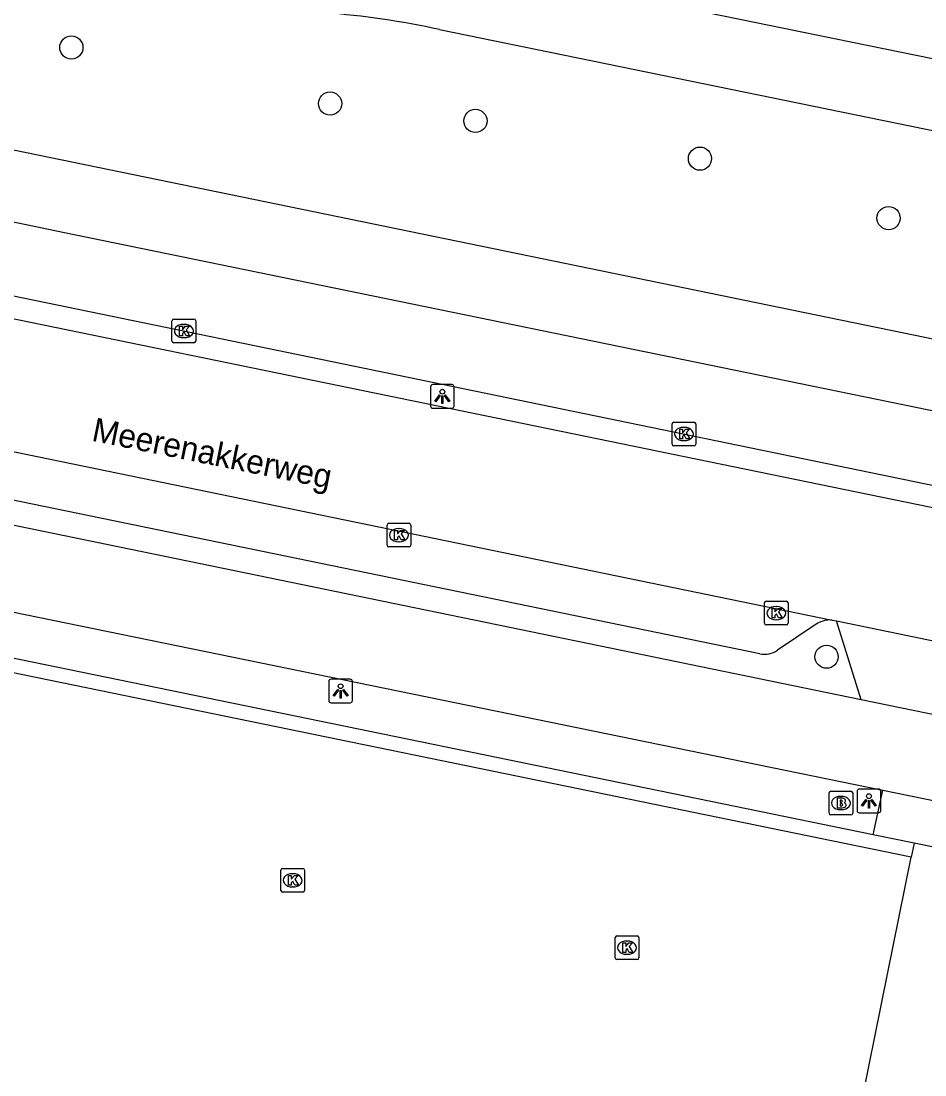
# Model space of a CAD drawing. Extents: x 157692 to 159670, y 381454 to 383289.
# Drawn here: x 158620.7 to 158658.83, y 382055.97 to 382100.44 of the extents above; entities that cross this region are included whole.
import ezdxf

# ---------------------------------------------------------------- set-up
doc = ezdxf.new("R2010")
doc.units = 0
for name, color, linetype in [('IMGEO_Boom', 7, 'Continuous'), ('IMGEO_Brandkraan', 7, 'Continuous'), ('IMGEO_Fietspad_gesloten', 7, 'Continuous'), ('IMGEO_Haag', 7, 'Continuous'), ('IMGEO_Kolk', 7, 'Continuous'), ('IMGEO_Lichtpunt', 7, 'Continuous'), ('IMGEO_Openbare_ruimte_label', 7, 'Continuous'), ('IMGEO_Parkeervlak_open', 7, 'Continuous'), ('IMGEO_Rijbaan_lokaal_open', 7, 'Continuous'), ('IMGEO_Rijbaan_regionaal_gesloten', 7, 'Continuous'), ('IMGEO_Voetpad_open', 7, 'Continuous')]:
    doc.layers.add(name, color=color, linetype=linetype)

msp = doc.modelspace()

# ---------------------------------------------------------------- linework, layer by layer
at = {"layer": 'IMGEO_Boom'}
for centre in [(158622.819, 382099.321), (158633.736, 382096.955), (158639.866, 382096.224), (158649.338, 382094.631), (158657.295, 382092.122), (158654.68, 382073.617)]:
    msp.add_circle(centre, 0.489, dxfattribs=at)
at = {"layer": 'IMGEO_Brandkraan'}
for p, q in [((158654.783, 382067.016), (158654.783, 382067.868)), ((158654.858, 382067.942), (158655.71, 382067.942)), ((158655.271, 382067.722), (158655.296, 382067.722)), ((158655.784, 382067.868), (158655.784, 382067.016)), ((158655.294, 382067.162), (158655.269, 382067.162)), ((158655.71, 382066.942), (158654.858, 382066.942))]:
    msp.add_line(p, q, dxfattribs=at)
for points in [[(158654.783, 382067.016), (158654.783, 382067.868)], [(158654.858, 382067.942), (158655.71, 382067.942)], [(158655.131, 382067.642), (158655.131, 382067.242), (158655.344, 382067.242)], [(158655.362, 382067.642), (158655.131, 382067.642)], [(158655.784, 382067.868), (158655.784, 382067.016)], [(158655.31, 382067.561), (158655.256, 382067.561), (158655.256, 382067.485)], [(158655.256, 382067.485), (158655.309, 382067.485)], [(158655.318, 382067.409), (158655.256, 382067.409), (158655.256, 382067.328)], [(158655.256, 382067.328), (158655.318, 382067.328)], [(158655.71, 382066.942), (158654.858, 382066.942)]]:
    msp.add_lwpolyline(points, dxfattribs=at)
for centre, radius, start, end in [((158654.86, 382067.866), 0.0765, 91.552, 178.448), ((158654.86, 382067.866), 0.0765, 91.552, 178.448), ((158655.366, 382067.497), 0.145, 59.4692, 91.5367), ((158655.391, 382067.544), 0.0922, 285.5137, 58.1501), ((158655.708, 382067.866), 0.0765, 1.552, 88.448), ((158655.708, 382067.866), 0.0765, 1.552, 88.448), ((158655.311, 382067.523), 0.0379, 267.8285, 90.9355), ((158655.319, 382067.368), 0.0404, 269.8759, 90.5077), ((158655.35, 382067.493), 0.251, 268.6676, 293.5347), ((158655.396, 382067.352), 0.105, 301.3115, 78.989), ((158654.86, 382067.018), 0.0765, 181.552, 268.448), ((158654.86, 382067.018), 0.0765, 181.552, 268.448), ((158655.708, 382067.018), 0.0765, 271.552, 358.448), ((158655.708, 382067.018), 0.0765, 271.552, 358.448)]:
    msp.add_arc(centre, radius, start, end, dxfattribs=at)
for centre, major_axis, ratio, start_param, end_param in [((158655.27, 382067.442), (-0.387, 0.002), 0.722429, 4.712389, 7.853982), ((158655.295, 382067.442), (-0.39, 0.002), 0.717154, 1.570796, 4.712389)]:
    msp.add_ellipse(centre, major_axis=major_axis, ratio=ratio, start_param=start_param, end_param=end_param, dxfattribs=at)
at = {"layer": 'IMGEO_Fietspad_gesloten'}
for points in [[(158533.524, 382092.807), (158567.173, 382086.396), (158657.056, 382067.984)], [(158656.145, 382071.8), (158599.36, 382083.49)], [(158657.056, 382067.984), (158692.348, 382060.756)]]:
    msp.add_lwpolyline(points, dxfattribs=at)
at = {"layer": 'IMGEO_Haag'}
msp.add_lwpolyline([(158658.251, 382065.165), (158656.531, 382065.514), (158574.936, 382082.265), (158570.839, 382083.106), (158565.823, 382083.768), (158561.047, 382084.02), (158557.322, 382083.532), (158553.579, 382082.999), (158549.351, 382081.923), (158544.304, 382079.926), (158539.307, 382077.53)], dxfattribs=at)
at = {"layer": 'IMGEO_Kolk'}
for p, q in [((158627.065, 382086.934), (158627.065, 382087.786)), ((158627.14, 382087.86), (158627.992, 382087.86)), ((158627.553, 382087.64), (158627.578, 382087.64)), ((158628.066, 382087.786), (158628.066, 382086.934)), ((158627.992, 382086.86), (158627.14, 382086.86)), ((158627.576, 382087.08), (158627.551, 382087.08)), ((158648.164, 382082.587), (158648.164, 382083.439)), ((158648.239, 382083.513), (158649.091, 382083.513)), ((158648.652, 382083.293), (158648.677, 382083.293)), ((158649.165, 382083.439), (158649.165, 382082.587)), ((158648.675, 382082.733), (158648.65, 382082.733)), ((158649.091, 382082.513), (158648.239, 382082.513)), ((158636.137, 382078.32), (158636.137, 382079.172)), ((158636.212, 382079.246), (158637.064, 382079.246)), ((158637.138, 382079.172), (158637.138, 382078.32)), ((158636.625, 382079.026), (158636.65, 382079.026)), ((158636.648, 382078.466), (158636.623, 382078.466)), ((158637.064, 382078.246), (158636.212, 382078.246)), ((158652.058, 382075.031), (158652.058, 382075.883)), ((158652.133, 382075.957), (158652.985, 382075.957)), ((158652.546, 382075.737), (158652.571, 382075.737)), ((158653.059, 382075.883), (158653.059, 382075.031)), ((158652.569, 382075.177), (158652.544, 382075.177)), ((158652.985, 382074.957), (158652.133, 382074.957)), ((158631.655, 382063.755), (158631.655, 382064.607)), ((158631.73, 382064.681), (158632.582, 382064.681)), ((158632.656, 382064.607), (158632.656, 382063.755)), ((158632.143, 382064.461), (158632.168, 382064.461)), ((158632.582, 382063.681), (158631.73, 382063.681)), ((158632.166, 382063.901), (158632.141, 382063.901)), ((158645.836, 382061.839), (158646.688, 382061.839)), ((158645.761, 382060.913), (158645.761, 382061.765)), ((158646.249, 382061.619), (158646.274, 382061.619)), ((158646.762, 382061.765), (158646.762, 382060.913)), ((158646.272, 382061.059), (158646.247, 382061.059)), ((158646.688, 382060.839), (158645.836, 382060.839))]:
    msp.add_line(p, q, dxfattribs=at)
for points in [[(158627.065, 382086.934), (158627.065, 382087.786)], [(158627.14, 382087.86), (158627.992, 382087.86)], [(158628.066, 382087.786), (158628.066, 382086.934)], [(158627.386, 382087.56), (158627.509, 382087.56), (158627.509, 382087.409), (158627.639, 382087.56), (158627.803, 382087.56), (158627.657, 382087.409), (158627.81, 382087.16), (158627.658, 382087.16), (158627.573, 382087.324), (158627.509, 382087.257), (158627.509, 382087.16), (158627.386, 382087.16), (158627.386, 382087.56)], [(158627.992, 382086.86), (158627.14, 382086.86)], [(158648.164, 382082.587), (158648.164, 382083.439)], [(158648.239, 382083.513), (158649.091, 382083.513)], [(158648.485, 382083.213), (158648.608, 382083.213), (158648.608, 382083.062), (158648.738, 382083.213), (158648.902, 382083.213), (158648.756, 382083.062), (158648.909, 382082.813), (158648.757, 382082.813), (158648.672, 382082.977), (158648.608, 382082.91), (158648.608, 382082.813), (158648.485, 382082.813), (158648.485, 382083.213)], [(158649.165, 382083.439), (158649.165, 382082.587)], [(158649.091, 382082.513), (158648.239, 382082.513)], [(158636.137, 382078.32), (158636.137, 382079.172)], [(158636.212, 382079.246), (158637.064, 382079.246)], [(158637.138, 382079.172), (158637.138, 382078.32)], [(158636.458, 382078.946), (158636.581, 382078.946), (158636.581, 382078.795), (158636.711, 382078.946), (158636.875, 382078.946), (158636.729, 382078.795), (158636.882, 382078.546), (158636.73, 382078.546), (158636.645, 382078.71), (158636.581, 382078.643), (158636.581, 382078.546), (158636.458, 382078.546), (158636.458, 382078.946)], [(158637.064, 382078.246), (158636.212, 382078.246)], [(158652.058, 382075.031), (158652.058, 382075.883)], [(158652.133, 382075.957), (158652.985, 382075.957)], [(158652.379, 382075.657), (158652.502, 382075.657), (158652.502, 382075.506), (158652.632, 382075.657), (158652.796, 382075.657), (158652.65, 382075.506), (158652.803, 382075.257), (158652.651, 382075.257), (158652.566, 382075.421), (158652.502, 382075.354), (158652.502, 382075.257), (158652.379, 382075.257), (158652.379, 382075.657)], [(158653.059, 382075.883), (158653.059, 382075.031)], [(158652.985, 382074.957), (158652.133, 382074.957)], [(158631.655, 382063.755), (158631.655, 382064.607)], [(158631.73, 382064.681), (158632.582, 382064.681)], [(158632.656, 382064.607), (158632.656, 382063.755)], [(158631.976, 382064.381), (158632.099, 382064.381), (158632.099, 382064.23), (158632.229, 382064.381), (158632.393, 382064.381), (158632.247, 382064.23), (158632.4, 382063.981), (158632.248, 382063.981), (158632.163, 382064.145), (158632.099, 382064.078), (158632.099, 382063.981), (158631.976, 382063.981), (158631.976, 382064.381)], [(158632.582, 382063.681), (158631.73, 382063.681)], [(158645.836, 382061.839), (158646.688, 382061.839)], [(158645.761, 382060.913), (158645.761, 382061.765)], [(158646.082, 382061.539), (158646.205, 382061.539), (158646.205, 382061.388), (158646.335, 382061.539), (158646.499, 382061.539), (158646.353, 382061.388), (158646.506, 382061.139), (158646.354, 382061.139), (158646.269, 382061.303), (158646.205, 382061.236), (158646.205, 382061.139), (158646.082, 382061.139), (158646.082, 382061.539)], [(158646.762, 382061.765), (158646.762, 382060.913)], [(158646.688, 382060.839), (158645.836, 382060.839)]]:
    msp.add_lwpolyline(points, dxfattribs=at)
for centre, start, end in [((158627.142, 382087.784), 91.552, 178.448), ((158627.142, 382087.784), 91.552, 178.448), ((158627.99, 382087.784), 1.552, 88.448), ((158627.99, 382087.784), 1.552, 88.448), ((158627.142, 382086.936), 181.552, 268.448), ((158627.142, 382086.936), 181.552, 268.448), ((158627.99, 382086.936), 271.552, 358.448), ((158627.99, 382086.936), 271.552, 358.448), ((158648.241, 382083.437), 91.552, 178.448), ((158648.241, 382083.437), 91.552, 178.448), ((158649.089, 382083.437), 1.552, 88.448), ((158649.089, 382083.437), 1.552, 88.448), ((158648.241, 382082.589), 181.552, 268.448), ((158648.241, 382082.589), 181.552, 268.448), ((158649.089, 382082.589), 271.552, 358.448), ((158649.089, 382082.589), 271.552, 358.448), ((158636.214, 382079.17), 91.552, 178.448), ((158636.214, 382079.17), 91.552, 178.448), ((158637.062, 382079.17), 1.552, 88.448), ((158637.062, 382079.17), 1.552, 88.448), ((158636.214, 382078.322), 181.552, 268.448), ((158636.214, 382078.322), 181.552, 268.448), ((158637.062, 382078.322), 271.552, 358.448), ((158637.062, 382078.322), 271.552, 358.448), ((158652.135, 382075.881), 91.552, 178.448), ((158652.135, 382075.881), 91.552, 178.448), ((158652.983, 382075.881), 1.552, 88.448), ((158652.983, 382075.881), 1.552, 88.448), ((158652.135, 382075.033), 181.552, 268.448), ((158652.135, 382075.033), 181.552, 268.448), ((158652.983, 382075.033), 271.552, 358.448), ((158652.983, 382075.033), 271.552, 358.448), ((158631.732, 382064.605), 91.552, 178.448), ((158631.732, 382064.605), 91.552, 178.448), ((158632.58, 382064.605), 1.552, 88.448), ((158632.58, 382064.605), 1.552, 88.448), ((158631.732, 382063.757), 181.552, 268.448), ((158631.732, 382063.757), 181.552, 268.448), ((158632.58, 382063.757), 271.552, 358.448), ((158632.58, 382063.757), 271.552, 358.448), ((158645.838, 382061.763), 91.552, 178.448), ((158645.838, 382061.763), 91.552, 178.448), ((158646.686, 382061.763), 1.552, 88.448), ((158646.686, 382061.763), 1.552, 88.448), ((158645.838, 382060.915), 181.552, 268.448), ((158645.838, 382060.915), 181.552, 268.448), ((158646.686, 382060.915), 271.552, 358.448), ((158646.686, 382060.915), 271.552, 358.448)]:
    msp.add_arc(centre, 0.0765, start, end, dxfattribs=at)
for centre, major_axis, ratio, start_param, end_param in [((158627.552, 382087.36), (-0.387, 0.002), 0.722429, 4.712389, 7.853982), ((158627.577, 382087.36), (-0.39, 0.002), 0.717154, 1.570796, 4.712389), ((158648.651, 382083.013), (-0.387, 0.002), 0.722429, 4.712389, 7.853982), ((158648.676, 382083.013), (-0.39, 0.002), 0.717154, 1.570796, 4.712389), ((158636.624, 382078.746), (-0.387, 0.002), 0.722429, 4.712389, 7.853982), ((158636.649, 382078.746), (-0.39, 0.002), 0.717154, 1.570796, 4.712389), ((158652.545, 382075.457), (-0.387, 0.002), 0.722429, 4.712389, 7.853982), ((158652.57, 382075.457), (-0.39, 0.002), 0.717154, 1.570796, 4.712389), ((158632.142, 382064.181), (-0.387, 0.002), 0.722429, 4.712389, 7.853982), ((158632.167, 382064.181), (-0.39, 0.002), 0.717154, 1.570796, 4.712389), ((158646.248, 382061.339), (-0.387, 0.002), 0.722429, 4.712389, 7.853982), ((158646.273, 382061.339), (-0.39, 0.002), 0.717154, 1.570796, 4.712389)]:
    msp.add_ellipse(centre, major_axis=major_axis, ratio=ratio, start_param=start_param, end_param=end_param, dxfattribs=at)
at = {"layer": 'IMGEO_Lichtpunt'}
for p, q in [((158637.971, 382085.001), (158637.971, 382084.194)), ((158637.971, 382085.001), (158637.971, 382084.194)), ((158638.873, 382085.096), (158638.065, 382085.096)), ((158638.873, 382085.096), (158638.065, 382085.096)), ((158638.967, 382084.194), (158638.967, 382085.001)), ((158638.967, 382084.194), (158638.967, 382085.001)), ((158638.065, 382084.1), (158638.873, 382084.1)), ((158638.065, 382084.1), (158638.873, 382084.1)), ((158633.681, 382072.574), (158633.681, 382071.767)), ((158633.681, 382072.574), (158633.681, 382071.767)), ((158634.583, 382072.669), (158633.775, 382072.669)), ((158634.583, 382072.669), (158633.775, 382072.669)), ((158634.677, 382071.767), (158634.677, 382072.574)), ((158634.677, 382071.767), (158634.677, 382072.574)), ((158633.775, 382071.673), (158634.583, 382071.673)), ((158633.775, 382071.673), (158634.583, 382071.673)), ((158655.966, 382067.934), (158655.966, 382067.127)), ((158655.966, 382067.934), (158655.966, 382067.127)), ((158656.868, 382068.029), (158656.06, 382068.029)), ((158656.868, 382068.029), (158656.06, 382068.029)), ((158656.962, 382067.127), (158656.962, 382067.934)), ((158656.962, 382067.127), (158656.962, 382067.934)), ((158656.06, 382067.033), (158656.868, 382067.033)), ((158656.06, 382067.033), (158656.868, 382067.033))]:
    msp.add_line(p, q, dxfattribs=at)
for points in [[(158638.345, 382084.665), (158638.384, 382084.637), (158638.196, 382084.375), (158638.158, 382084.402), (158638.345, 382084.665)], [(158638.447, 382084.617), (158638.494, 382084.617), (158638.494, 382084.295), (158638.447, 382084.295), (158638.447, 382084.617)], [(158638.557, 382084.637), (158638.595, 382084.664), (158638.782, 382084.402), (158638.743, 382084.374), (158638.557, 382084.637)], [(158634.055, 382072.238), (158634.094, 382072.21), (158633.906, 382071.948), (158633.868, 382071.975), (158634.055, 382072.238)], [(158634.157, 382072.19), (158634.204, 382072.19), (158634.204, 382071.868), (158634.157, 382071.868), (158634.157, 382072.19)], [(158634.267, 382072.21), (158634.305, 382072.237), (158634.492, 382071.975), (158634.453, 382071.947), (158634.267, 382072.21)], [(158656.34, 382067.598), (158656.379, 382067.57), (158656.191, 382067.308), (158656.153, 382067.335), (158656.34, 382067.598)], [(158656.552, 382067.57), (158656.59, 382067.597), (158656.777, 382067.335), (158656.738, 382067.307), (158656.552, 382067.57)], [(158656.442, 382067.55), (158656.489, 382067.55), (158656.489, 382067.228), (158656.442, 382067.228), (158656.442, 382067.55)]]:
    msp.add_lwpolyline(points, dxfattribs=at)
for centre in [(158638.47, 382084.799), (158634.18, 382072.372), (158656.465, 382067.732)]:
    msp.add_circle(centre, 0.0994, dxfattribs=at)
for centre, start, end in [((158638.065, 382085.001), 90, 180), ((158638.065, 382085.001), 90, 180), ((158638.873, 382085.001), 0, 90), ((158638.873, 382085.001), 0, 90), ((158638.065, 382084.194), 180, 270), ((158638.065, 382084.194), 180, 270), ((158638.873, 382084.194), 270, 0), ((158638.873, 382084.194), 270, 360), ((158633.775, 382072.574), 90, 180), ((158633.775, 382072.574), 90, 180), ((158634.583, 382072.574), 0, 90), ((158634.583, 382072.574), 0, 90), ((158633.775, 382071.767), 180, 270), ((158633.775, 382071.767), 180, 270), ((158634.583, 382071.767), 270, 0), ((158634.583, 382071.767), 270, 360), ((158656.06, 382067.934), 90, 180), ((158656.06, 382067.934), 90, 180), ((158656.868, 382067.934), 0, 90), ((158656.868, 382067.934), 0, 90), ((158656.06, 382067.127), 180, 270), ((158656.06, 382067.127), 180, 270), ((158656.868, 382067.127), 270, 0), ((158656.868, 382067.127), 270, 360)]:
    msp.add_arc(centre, 0.0946, start, end, dxfattribs=at)
at = {"layer": 'IMGEO_Parkeervlak_open'}
for points in [[(158651.862, 382073.744), (158599.702, 382084.466), (158599.637, 382084.492)], [(158654.239, 382074.984), (158652.612, 382073.887)]]:
    msp.add_lwpolyline(points, dxfattribs=at)
for centre, radius, start, end in [((158654.812, 382074.184), 0.984, 84.1681, 125.6206), ((158652.074, 382074.672), 0.952, 257.1467, 304.443)]:
    msp.add_arc(centre, radius, start, end, dxfattribs=at)
at = {"layer": 'IMGEO_Rijbaan_lokaal_open'}
for points in [[(158774.468, 382056.03), (158771.914, 382056.729), (158599.236, 382092.209)], [(158597.523, 382086.973), (158654.912, 382075.163)], [(158654.912, 382075.163), (158655.104, 382075.124)], [(158655.104, 382075.124), (158697.271, 382066.421)], [(158656.145, 382071.8), (158655.104, 382075.124)], [(158694.964, 382063.831), (158656.145, 382071.8)], [(158658.369, 382065.753), (158658.251, 382065.165)], [(158662.116, 382064.993), (158658.369, 382065.753)], [(158652.182, 382035.481), (158655.122, 382049.713), (158657.003, 382058.968), (158658.251, 382065.165)]]:
    msp.add_lwpolyline(points, dxfattribs=at)
at = {"layer": 'IMGEO_Rijbaan_regionaal_gesloten'}
for points in [[(158678.367, 382094.92), (158638.613, 382103.052), (158635.307, 382103.698), (158633.519, 382104.023), (158626.935, 382105.205), (158617.449, 382106.752), (158616.181, 382106.959), (158614.278, 382107.25), (158612.349, 382107.545), (158605.202, 382108.529), (158604.424, 382108.621), (158600.665, 382109.068), (158598.421, 382109.348), (158555.79, 382114.433), (158544.073, 382116.001)], [(158694.915, 382076.653), (158622.531, 382091.496), (158609.848, 382094.151), (158606.057, 382094.876), (158598.418, 382096.431), (158594.654, 382097.166), (158590.801, 382097.831), (158589.111, 382098.117), (158587.099, 382098.457), (158583.058, 382099.038), (158554.031, 382102.561), (158552.923, 382102.699), (158549.755, 382103.091), (158542.731, 382103.96)], [(158789.108, 382059.781), (158785.616, 382060.813), (158779.77, 382062.223), (158601.14, 382098.944), (158595.092, 382100.086)], [(158638.357, 382100.078), (158771.214, 382072.861)], [(158585.035, 382095.717), (158600.841, 382092.865), (158711.762, 382070.015), (158773.956, 382057.298), (158778.07, 382056.314)]]:
    msp.add_lwpolyline(points, dxfattribs=at)
msp.add_arc((158630.823, 382065.426), 35.462, 77.7336, 85.6624, dxfattribs=at)
at = {"layer": 'IMGEO_Voetpad_open'}
for points in [[(158656.651, 382066.102), (158575.057, 382082.853), (158570.941, 382083.698)], [(158656.651, 382066.102), (158657.056, 382067.984)], [(158658.369, 382065.753), (158656.651, 382066.102)]]:
    msp.add_lwpolyline(points, dxfattribs=at)

# ---------------------------------------------------------------- texts
at = {"layer": 'IMGEO_Openbare_ruimte_label'}
msp.add_text('Meerenakkerweg', height=1, rotation=348.5777, dxfattribs=at).set_placement((158623.639, 382082.735))

doc.saveas('drawing.dxf')
